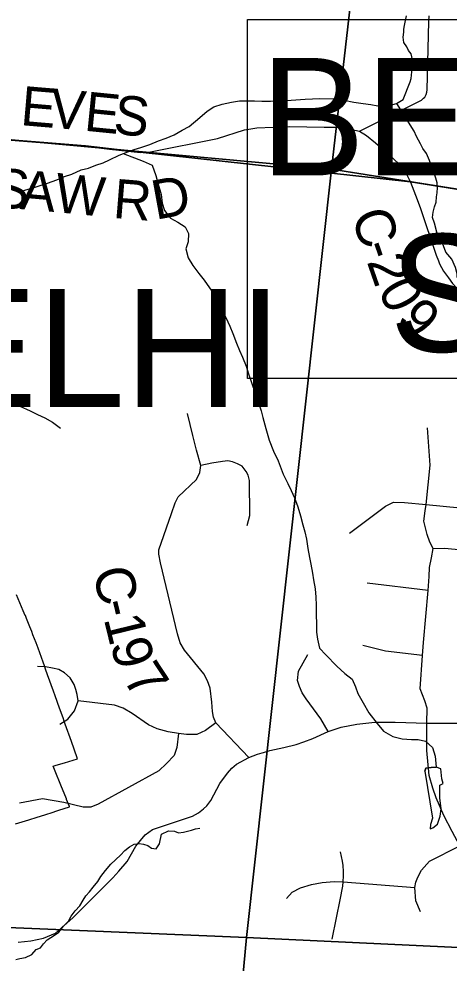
# Model space of a CAD drawing. Extents: x 0 to 43.4, y -8.1 to 22.
# Drawn here: x 4.286 to 4.908, y 16.475 to 17.842 of the extents above; entities that cross this region are included whole.
import ezdxf

# ---------------------------------------------------------------- set-up
doc = ezdxf.new("R2010")
doc.units = 0
for name, color, linetype in [('GM_X_Corporation', 7, 'Continuous'), ('GM_X_County_Road', 7, 'Continuous'), ('GM_X_County_Road_Text', 7, 'Continuous'), ('GM_X_Minor_Lake', 7, 'Continuous'), ('GM_X_Minor_River', 7, 'Continuous'), ('GM_X_Township_Road', 7, 'Continuous'), ('GM_X_Township_Text', 7, 'Continuous'), ('SH_Masking', 7, 'Continuous'), ('SH_Text', 7, 'Continuous')]:
    doc.layers.add(name, color=color, linetype=linetype)

msp = doc.modelspace()

# ---------------------------------------------------------------- linework, layer by layer
at = {"layer": 'GM_X_Corporation'}
for points in [[(4.8473, 18.579), (4.7377, 17.6242), (3.7435, 17.7155), (3.8378, 18.6959)], [(4.8473, 18.579), (5.8893, 18.4791), (5.7989, 17.456), (4.7377, 17.6242)], [(4.7377, 17.6242), (4.6148, 16.5127), (3.671, 16.5519), (3.6538, 16.5644), (3.6462, 16.5775), (3.6418, 16.5844), (3.7435, 17.7155)], [(5.7989, 17.456), (5.7092, 16.4607), (4.6148, 16.5127), (4.7377, 17.6242)]]:
    msp.add_lwpolyline(points, close=True, dxfattribs=at)
for points in [[(6.9337, 17.3322), (6.8401, 17.341), (6.7303, 17.3528), (6.5022, 17.378), (6.4189, 17.3857), (6.2062, 17.4054), (6.1906, 17.4067), (5.7944, 17.4564), (5.4373, 17.5131), (4.8521, 17.6061), (4.4612, 17.6488), (4.3821, 17.6581), (4.1644, 17.6753)], [(4.1644, 17.6753), (4.3821, 17.6581), (4.4612, 17.6488), (4.8521, 17.6061), (5.4373, 17.5131), (5.7944, 17.4564), (6.1906, 17.4067), (6.2062, 17.4054), (6.4189, 17.3857), (6.5022, 17.378), (6.7303, 17.3528), (6.8401, 17.341), (6.9337, 17.3322)], [(4.2808, 16.6769), (4.3, 16.683), (4.3122, 16.6868), (4.3229, 16.6902), (4.3351, 16.6941), (4.3392, 16.6954), (4.3432, 16.6967), (4.359, 16.7018), (4.359, 16.7019), (4.3547, 16.7123), (4.3544, 16.7131), (4.3463, 16.733), (4.3381, 16.753), (4.335, 16.7604), (4.3396, 16.7618), (4.3517, 16.7655), (4.3639, 16.7692), (4.3705, 16.7712), (4.37, 16.7727), (4.3616, 16.796), (4.3527, 16.821), (4.351, 16.8256), (4.3494, 16.8302), (4.3443, 16.8446), (4.338, 16.8621), (4.3355, 16.8692), (4.327, 16.8928), (4.3242, 16.9006), (4.3224, 16.9058), (4.3205, 16.911), (4.3133, 16.9313), (4.3105, 16.9391), (4.3059, 16.9507), (4.3041, 16.9552), (4.3012, 16.9623), (4.2966, 16.9739), (4.2949, 16.9783), (4.2947, 16.9787), (4.2919, 16.9854), (4.2871, 16.9968), (4.2822, 17.0082)], [(3.671, 16.5519), (4.6148, 16.5127), (4.5615, 15.9381)], [(4.5615, 15.9381), (4.6148, 16.5127), (5.7092, 16.4607)]]:
    msp.add_lwpolyline(points, dxfattribs=at)
at = {"layer": 'GM_X_County_Road'}
for points in [[(4.7784, 17.6791), (4.868, 17.7243), (4.8711, 17.727), (4.8727, 17.7285), (4.8749, 17.7323), (4.8756, 17.7359), (4.8763, 17.7391), (4.8786, 17.8378), (4.8794, 17.8464)], [(3.9409, 17.6933), (4.0718, 17.6825), (4.1647, 17.6748), (4.3824, 17.6576), (4.4168, 17.6535)], [(4.4168, 17.6535), (4.4614, 17.6483), (4.4758, 17.6493), (4.573, 17.6686), (4.6118, 17.6811), (4.621, 17.6829), (4.6299, 17.684), (4.6769, 17.6859), (4.7272, 17.6849), (4.7442, 17.6849), (4.7505, 17.684), (4.7568, 17.6835), (4.7631, 17.6828), (4.7784, 17.6791), (4.7885, 17.673), (4.8014, 17.6625), (4.8162, 17.6497), (4.8353, 17.6318), (4.8442, 17.622), (4.8523, 17.6056), (4.8596, 17.5869), (4.8662, 17.5688), (4.8895, 17.4997), (4.8925, 17.4918)], [(4.8925, 17.4918), (4.8942, 17.4873), (4.8997, 17.4769), (4.9071, 17.4673), (4.9128, 17.4591), (4.9202, 17.4514)], [(4.6183, 16.7729), (4.5705, 16.8234), (4.5673, 16.8314), (4.5659, 16.8396), (4.5647, 16.8531), (4.5625, 16.8732), (4.5587, 16.8838), (4.5533, 16.8939), (4.5253, 16.9282), (4.519, 16.9389), (4.5152, 16.9519), (4.4903, 17.0548), (4.4879, 17.0673), (4.4881, 17.0736), (4.5065, 17.1263), (4.5116, 17.1417), (4.5162, 17.1504), (4.5427, 17.1753), (4.5473, 17.1852), (4.549, 17.1953), (4.5427, 17.2175), (4.5372, 17.2388), (4.5294, 17.2707)], [(4.6374, 16.7798), (4.6393, 16.7804), (4.6488, 16.7832), (4.6689, 16.7877), (4.6868, 16.7916), (4.698, 16.7955), (4.7108, 16.8004), (4.7329, 16.8105), (4.7521, 16.8171), (4.7744, 16.8211), (4.8004, 16.8239), (4.8298, 16.8239), (4.8756, 16.8228), (4.9193, 16.8226), (4.9416, 16.8253), (4.9543, 16.8284), (4.9651, 16.8339), (4.9791, 16.8397), (4.9919, 16.8418), (5.0061, 16.844), (5.0259, 16.8461), (5.1922, 16.8534)], [(4.2846, 16.5056), (4.3029, 16.5075), (4.3211, 16.5116), (4.3384, 16.5188), (4.3635, 16.541), (4.4217, 16.5989), (4.4302, 16.6086), (4.4421, 16.6223), (4.4549, 16.6448), (4.4683, 16.6609), (4.479, 16.6686), (4.5369, 16.6883), (4.5412, 16.6904), (4.5453, 16.6929), (4.5525, 16.6987), (4.5575, 16.703), (4.5631, 16.7107), (4.5764, 16.7352), (4.5872, 16.7502), (4.5935, 16.7575), (4.6003, 16.7633), (4.6183, 16.7729), (4.6306, 16.7776), (4.6374, 16.7798)]]:
    msp.add_lwpolyline(points, dxfattribs=at)
at = {"layer": 'GM_X_Minor_Lake'}
for points in [[(4.8728, 16.7531), (4.8839, 16.6852), (4.881, 16.6761), (4.8808, 16.6697), (4.8847, 16.6711), (4.8913, 16.6766), (4.895, 16.6879), (4.8964, 16.6985), (4.8946, 16.7145), (4.8947, 16.7331), (4.8993, 16.7353), (4.8976, 16.7421), (4.8961, 16.7566), (4.8891, 16.7591)], [(4.882, 16.7584), (4.8744, 16.7576), (4.8728, 16.7531)], [(4.8728, 16.7531), (4.8744, 16.7576), (4.8821, 16.7584)], [(4.8891, 16.7591), (4.882, 16.7584)], [(4.882, 16.7584), (4.8891, 16.7591)]]:
    msp.add_lwpolyline(points, dxfattribs=at)
at = {"layer": 'GM_X_Minor_River'}
for points in [[(4.8415, 17.7253), (4.8516, 17.7508), (4.8529, 17.7553), (4.8534, 17.7602), (4.8543, 17.7651), (4.8549, 17.7697), (4.8555, 17.7765), (4.8553, 17.7826), (4.8539, 17.7868), (4.8533, 17.791), (4.8493, 17.7961), (4.8469, 17.8015), (4.8425, 17.8077), (4.8416, 17.8154), (4.8423, 17.8226), (4.8424, 17.8267), (4.8434, 17.832), (4.8443, 17.8369), (4.8465, 17.8464)], [(4.2848, 17.5912), (4.2958, 17.5943), (4.3077, 17.5978), (4.3176, 17.601), (4.3272, 17.6041), (4.3406, 17.6091), (4.3517, 17.6138), (4.3621, 17.6173), (4.3759, 17.6234), (4.3862, 17.6258), (4.3969, 17.6301), (4.4073, 17.6337), (4.4169, 17.638), (4.4307, 17.6445), (4.443, 17.6495), (4.4526, 17.653), (4.4621, 17.6558), (4.4748, 17.6601), (4.4874, 17.6651), (4.4985, 17.6694), (4.51, 17.674), (4.5216, 17.6806), (4.532, 17.686), (4.5475, 17.6989), (4.5579, 17.7081), (4.5676, 17.7144), (4.5798, 17.7186), (4.5932, 17.7213), (4.6046, 17.7233), (4.616, 17.7234), (4.6266, 17.7231), (4.6369, 17.7225), (4.6498, 17.7229), (4.6601, 17.7234), (4.6726, 17.7239), (4.7, 17.7255), (4.7212, 17.7265), (4.7413, 17.726), (4.7561, 17.7241), (4.7701, 17.7214), (4.7837, 17.7192), (4.7946, 17.7178), (4.8048, 17.716), (4.8193, 17.716), (4.8319, 17.7191), (4.8415, 17.7253)], [(4.8987, 17.5172), (4.8931, 17.5252), (4.8902, 17.5333), (4.8867, 17.5463), (4.8841, 17.5543), (4.885, 17.5619), (4.8867, 17.5698), (4.8891, 17.5766), (4.89, 17.5842), (4.8909, 17.5899), (4.8914, 17.5979), (4.8908, 17.6047), (4.889, 17.6112), (4.8861, 17.6204), (4.8824, 17.6281), (4.8795, 17.6369), (4.8751, 17.6468), (4.8699, 17.6541), (4.8666, 17.661), (4.8607, 17.6714), (4.8574, 17.6791), (4.8325, 17.7195)], [(4.4365, 17.6468), (4.4654, 17.636), (4.4782, 17.63), (4.4839, 17.615), (4.4869, 17.6024), (4.4915, 17.5879), (4.4931, 17.5753), (4.4962, 17.5646), (4.5047, 17.5534), (4.5155, 17.5474), (4.526, 17.5411), (4.5311, 17.5314), (4.5304, 17.5193), (4.5271, 17.5091), (4.5305, 17.4961), (4.5371, 17.485), (4.5459, 17.4733), (4.5536, 17.4637), (4.5683, 17.4428), (4.5741, 17.4331), (4.5795, 17.4201), (4.5849, 17.4097), (4.5907, 17.397), (4.5949, 17.3863), (4.6003, 17.3725), (4.6046, 17.3621), (4.6089, 17.3521), (4.6142, 17.3395), (4.6178, 17.3284), (4.622, 17.3154), (4.6319, 17.2878), (4.6361, 17.2747), (4.6385, 17.2648), (4.6431, 17.2491), (4.6479, 17.2323), (4.654, 17.2162), (4.6605, 17.2024), (4.6679, 17.1828), (4.6748, 17.1697), (4.6795, 17.1593), (4.6845, 17.1486), (4.6891, 17.1359), (4.693, 17.1225), (4.6964, 17.1095), (4.6992, 17.0996), (4.7016, 17.0889), (4.7036, 17.0756), (4.7059, 17.0626), (4.7079, 17.0527), (4.7106, 17.0397), (4.7119, 17.0302), (4.7142, 17.0172), (4.715, 17.005), (4.7155, 16.9932), (4.7159, 16.9807), (4.7163, 16.9651), (4.7164, 16.9545), (4.7177, 16.9442), (4.7204, 16.9312), (4.7296, 16.9215), (4.7455, 16.9051), (4.7574, 16.8946), (4.7678, 16.8863), (4.7728, 16.8752), (4.776, 16.8656), (4.7836, 16.8521), (4.792, 16.8375), (4.8038, 16.822), (4.813, 16.8112), (4.8264, 16.8032), (4.84, 16.8002), (4.8537, 16.7991), (4.8631, 16.7989), (4.8741, 16.7967), (4.8841, 16.7873), (4.888, 16.7747), (4.8891, 16.7591)], [(4.9196, 17.4678), (4.9197, 17.4731), (4.9172, 17.4819), (4.912, 17.4941), (4.9034, 17.5042), (4.8987, 17.5172)], [(4.2721, 17.2865), (4.2868, 17.2816), (4.3018, 17.2744), (4.3126, 17.2695), (4.3231, 17.2647), (4.3344, 17.2584), (4.3459, 17.2497)], [(4.281, 16.4805), (4.2868, 16.4823), (4.2949, 16.4837), (4.3041, 16.4881), (4.3107, 16.4952), (4.3169, 16.4978), (4.3212, 16.5034), (4.3266, 16.509), (4.3371, 16.5157), (4.3436, 16.5205), (4.3499, 16.5291), (4.3573, 16.5362), (4.3612, 16.5434), (4.3671, 16.5512), (4.3737, 16.5583), (4.3785, 16.5666), (4.3824, 16.5726), (4.3878, 16.5786), (4.3929, 16.5854), (4.3996, 16.5936), (4.4039, 16.6008), (4.4109, 16.6094), (4.4187, 16.6187), (4.4327, 16.6318), (4.439, 16.6385), (4.4456, 16.6437), (4.4525, 16.6474), (4.4598, 16.6488), (4.4659, 16.6475), (4.4719, 16.6455), (4.4776, 16.6416), (4.4841, 16.6408), (4.4888, 16.6483), (4.4917, 16.6623), (4.5021, 16.667), (4.5109, 16.6665), (4.5166, 16.6641), (4.5235, 16.6651), (4.5353, 16.668), (4.5411, 16.6698)], [(4.5411, 16.6698), (4.5472, 16.6708)]]:
    msp.add_lwpolyline(points, dxfattribs=at)
at = {"layer": 'GM_X_Township_Road'}
for p, q in [((4.8777, 17.0148), (4.7896, 17.0255)), ((4.7549, 16.5932), (4.8586, 16.5847))]:
    msp.add_line(p, q, dxfattribs=at)
for points in [[(4.8736, 17.1297), (4.875, 17.1389), (4.8805, 17.1958), (4.8768, 17.2499)], [(4.616, 17.1088), (4.6197, 17.1233), (4.6194, 17.1738), (4.6174, 17.1813), (4.6142, 17.1869), (4.6084, 17.1944), (4.602, 17.198), (4.5946, 17.2007), (4.5878, 17.2021), (4.5804, 17.2014), (4.5646, 17.1987), (4.549, 17.1953)], [(4.7641, 17.0974), (4.8158, 17.1369), (4.8278, 17.1426), (4.8434, 17.1422), (4.875, 17.1389), (5.0222, 17.1245), (5.0478, 17.121), (5.0567, 17.1185), (5.0639, 17.1134), (5.0709, 17.1043), (5.0738, 17.0958), (5.0748, 17.088), (5.0742, 17.0787), (5.0734, 17.0589)], [(4.9404, 16.6092), (4.9234, 16.6454), (4.9123, 16.6659), (4.9003, 16.6892), (4.8894, 16.7145), (4.8843, 16.7285), (4.8794, 16.7469), (4.8758, 16.7832), (4.8756, 16.8228), (4.8761, 16.8442), (4.8731, 16.8548), (4.8661, 16.8722), (4.8693, 16.9205), (4.8711, 16.9392), (4.8777, 17.0148), (4.8791, 17.0348), (4.8797, 17.0478), (4.8824, 17.0619), (4.8849, 17.0754), (4.8801, 17.0845), (4.8764, 17.0958), (4.8713, 17.115), (4.8736, 17.1297)], [(4.8849, 17.0754), (4.902, 17.0758), (5.0734, 17.0589), (5.0911, 17.0568), (5.1035, 17.0552), (5.1158, 17.0564), (5.134, 17.0614), (5.1501, 17.0651), (5.2081, 17.0602)], [(4.8693, 16.9205), (4.8162, 16.9268), (4.783, 16.9349)], [(4.7329, 16.8105), (4.7223, 16.8288), (4.7011, 16.8577), (4.6952, 16.8665), (4.6914, 16.8758), (4.6889, 16.8844), (4.6903, 16.8977), (4.7034, 16.922)], [(4.345, 16.821), (4.3562, 16.8287), (4.3661, 16.8406), (4.3713, 16.8551), (4.3698, 16.8641), (4.368, 16.8712), (4.3657, 16.8788), (4.36, 16.8885), (4.3517, 16.8953), (4.3432, 16.9004), (4.3344, 16.9025), (4.3241, 16.9044), (4.3127, 16.9047)], [(4.5705, 16.8234), (4.5556, 16.8123), (4.5431, 16.8065), (4.528, 16.8062), (4.5165, 16.8078), (4.5016, 16.8103), (4.4855, 16.8144), (4.4731, 16.8202), (4.4496, 16.8365), (4.4363, 16.8446), (4.4237, 16.8487), (4.3713, 16.8551)], [(4.5165, 16.8078), (4.5142, 16.7874), (4.5101, 16.7759), (4.4991, 16.7641), (4.4882, 16.7538), (4.4004, 16.7054), (4.3899, 16.701), (4.3785, 16.701), (4.3504, 16.7077)], [(4.8668, 16.5497), (4.8598, 16.5657), (4.8586, 16.5847), (4.8599, 16.5927), (4.8626, 16.5997), (4.8683, 16.6101), (4.8796, 16.6231), (4.9234, 16.6454), (4.9422, 16.6556), (4.9497, 16.6592), (4.9571, 16.665), (4.9641, 16.6751), (4.969, 16.69), (4.9696, 16.704), (4.9655, 16.7213), (4.9573, 16.7506)], [(4.3504, 16.7077), (4.3196, 16.7134), (4.2866, 16.707)], [(4.7549, 16.5932), (4.7554, 16.602), (4.755, 16.6082), (4.7549, 16.6165), (4.7539, 16.6231), (4.751, 16.6365)], [(4.6729, 16.569), (4.6811, 16.5783), (4.6929, 16.5843), (4.7091, 16.5891), (4.7243, 16.5923), (4.7416, 16.5938), (4.7549, 16.5932)], [(4.7387, 16.5102), (4.7453, 16.541), (4.7506, 16.5672), (4.7541, 16.5866), (4.7549, 16.5932)]]:
    msp.add_lwpolyline(points, dxfattribs=at)
at = {"layer": 'SH_Masking'}
msp.add_lwpolyline([(4.6164, 17.8409), (6.3738, 17.8409), (6.3738, 17.3215), (4.6164, 17.3215)], close=True, dxfattribs=at)
at = {"layer": 'SH_Text'}
msp.add_lwpolyline([(4.6164, 17.8409), (6.3738, 17.8409), (6.3738, 17.3215), (4.6164, 17.3215)], close=True, dxfattribs=at)

# ---------------------------------------------------------------- texts
at = {"layer": 'GM_X_County_Road_Text'}
for s, rotation, p in [('E', 355.1515, (4.2867, 17.6882)), ('V', 354.9135, (4.329, 17.6847)), ('E', 354.3036, (4.3787, 17.6802)), ('S', 353.8899, (4.4209, 17.676)), ('S', 355.1907, (4.248, 17.5699)), ('A', 355.0762, (4.2862, 17.5667)), ('W', 354.4942, (4.3359, 17.5624)), ('D', 10.3848, (4.4833, 17.5509)), ('R', 355.3878, (4.4206, 17.5539)), ('C', 289.0283, (4.7657, 17.5571)), ('-', 289.045, (4.781, 17.513)), ('2', 289.1904, (4.7886, 17.4908)), ('0', 297.8054, (4.8038, 17.4492)), ('9', 312.5869, (4.8294, 17.4052)), ('C', 282.8865, (4.3921, 17.0431)), ('-', 283.6044, (4.4027, 16.9968)), ('1', 283.7063, (4.4082, 16.974)), ('9', 286.1447, (4.4172, 16.9375)), ('7', 303.3685, (4.4347, 16.887))]:
    msp.add_text(s, height=0.0568, rotation=rotation, dxfattribs=at).set_placement(p)
at = {"layer": 'GM_X_Township_Text'}
msp.add_text('DELHI', height=0.17045, rotation=0, dxfattribs=at).set_placement((3.9954, 17.2803))
at = {"layer": 'SH_Text'}
for s, p in [('BEGIN PROJECT', (4.6347, 17.6152)), ('STA. 114+00', (4.8216, 17.3602))]:
    msp.add_text(s, height=0.17, dxfattribs=at).set_placement(p)

doc.saveas('drawing.dxf')
